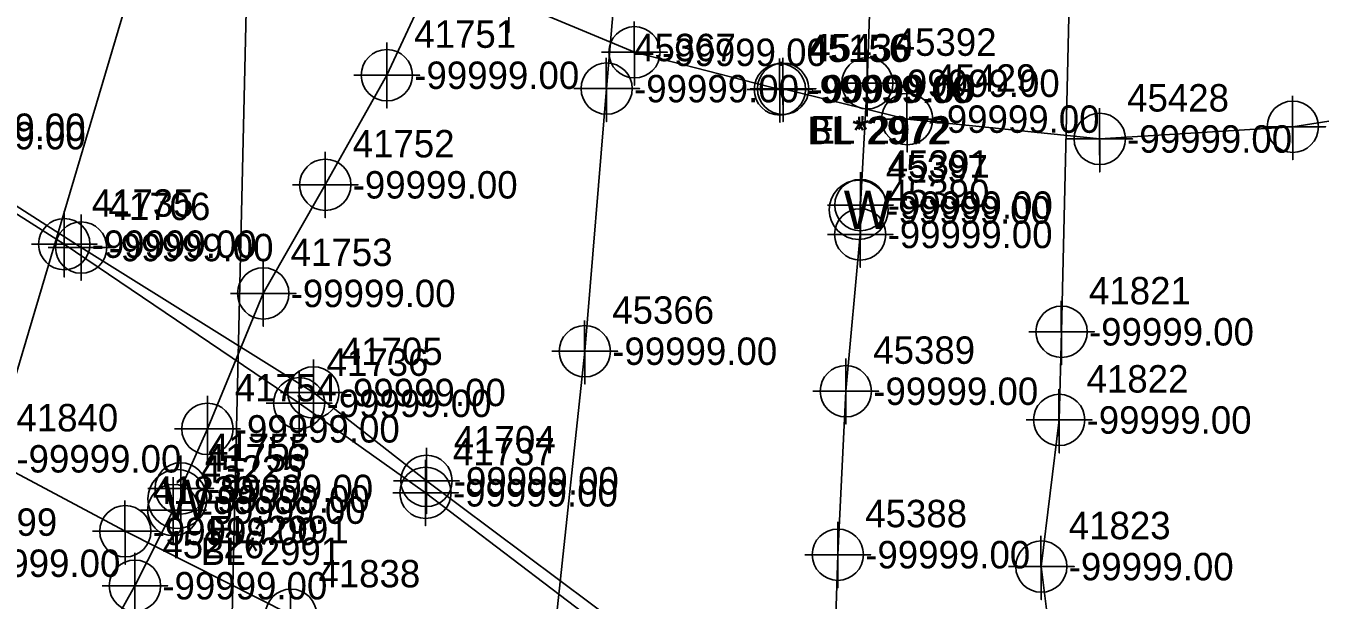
# Model space of a CAD drawing. Extents: x 2083698 to 2094313, y 743246 to 752873.
# Drawn here: x 2093554.6 to 2093672.8, y 743931 to 743983.3 of the extents above; entities that cross this region are included whole.
import ezdxf

# ---------------------------------------------------------------- set-up
doc = ezdxf.new("R2010")
doc.units = 0
for name, color, linetype in [('COGO Default Point Number', 7, 'Continuous'), ('Default Symbol CELL', 7, 'Continuous'), ('Default Symbol Cogo Number', 7, 'Continuous'), ('Exist Property Line', 7, 'Continuous'), ('Exist Property Line Leader', 7, 'Continuous'), ('Exist Right of Way Line', 7, 'Continuous'), ('Exist Right of Way Line Leader', 7, 'Continuous'), ('Exist Right of Way Line Text', 7, 'Continuous'), ('Exist Right of Way Width CELL', 7, 'Continuous'), ('Exist Utilities Power Pole Cogo Comment', 7, 'Continuous'), ('Exist Utilities Power Pole Cogo Elevation', 7, 'Continuous'), ('Exist Utilities Power Pole Cogo Number', 7, 'Continuous'), ('Exist Utilities Power UG Cable SUE LOS C', 7, 'Continuous'), ('Exist Utilities Telephone UG Conduit SUE LOS B', 7, 'Continuous'), ('Exist Utilities Telephone UG Conduit SUE LOS D', 7, 'Continuous'), ('Exist Utilities TV UG Cable SUE LOS B', 7, 'Continuous'), ('Exist Utilities Water UG Line SUE LOS B', 7, 'Continuous'), ('Scratch_Level_2', 7, 'Continuous'), ('Scratch_Level_3', 7, 'Continuous')]:
    doc.layers.add(name, color=color, linetype=linetype)

msp = doc.modelspace()

# ---------------------------------------------------------------- linework, layer by layer
at = {"layer": 'COGO Default Point Number'}
for points in [[(2093587.59, 743981.82), (2093587.59, 743975.82), (2093587.59, 743978.82), (2093590.59, 743978.82), (2093584.59, 743978.82)], [(2093631.44, 743981.09), (2093631.44, 743975.09), (2093631.44, 743978.09), (2093634.44, 743978.09), (2093628.44, 743978.09)], [(2093581.97, 743971.83), (2093581.97, 743965.83), (2093581.97, 743968.83), (2093584.97, 743968.83), (2093578.97, 743968.83)], [(2093630.81, 743969.98), (2093630.81, 743963.98), (2093630.81, 743966.98), (2093633.81, 743966.98), (2093627.81, 743966.98)], [(2093630.79, 743967.31), (2093630.79, 743961.31), (2093630.79, 743964.31), (2093633.79, 743964.31), (2093627.79, 743964.31)], [(2093576.31, 743961.93), (2093576.31, 743955.93), (2093576.31, 743958.93), (2093579.31, 743958.93), (2093573.31, 743958.93)], [(2093629.48, 743953.01), (2093629.48, 743947.01), (2093629.48, 743950.01), (2093632.48, 743950.01), (2093626.48, 743950.01)], [(2093571.21, 743949.58), (2093571.21, 743943.58), (2093571.21, 743946.58), (2093574.21, 743946.58), (2093568.21, 743946.58)], [(2093568.78, 743944.15), (2093568.78, 743938.15), (2093568.78, 743941.15), (2093571.78, 743941.15), (2093565.78, 743941.15)], [(2093568.1, 743942.17), (2093568.1, 743936.17), (2093568.1, 743939.17), (2093571.1, 743939.17), (2093565.1, 743939.17)], [(2093628.75, 743938.11), (2093628.75, 743932.11), (2093628.75, 743935.11), (2093631.75, 743935.11), (2093625.75, 743935.11)], [(2093564.6, 743935.28), (2093564.6, 743929.28), (2093564.6, 743932.28), (2093567.6, 743932.28), (2093561.6, 743932.28)]]:
    msp.add_lwpolyline(points, dxfattribs=at)
for centre in [(2093587.59, 743978.82), (2093631.44, 743978.09), (2093581.97, 743968.83), (2093630.81, 743966.98), (2093630.79, 743964.31), (2093576.31, 743958.93), (2093629.48, 743950.01), (2093571.21, 743946.58), (2093568.78, 743941.15), (2093568.1, 743939.17), (2093628.75, 743935.11), (2093564.6, 743932.28)]:
    msp.add_circle(centre, 2.34, dxfattribs=at)
at = {"layer": 'Exist Property Line Leader'}
for points in [[(2093558.15, 743966.42), (2093558.15, 743960.42), (2093558.15, 743963.42), (2093561.15, 743963.42), (2093555.15, 743963.42)], [(2093559.69, 743966.11), (2093559.69, 743960.11), (2093559.69, 743963.11), (2093562.69, 743963.11), (2093556.69, 743963.11)], [(2093580.89, 743952.9), (2093580.89, 743946.9), (2093580.89, 743949.9), (2093583.89, 743949.9), (2093577.89, 743949.9)], [(2093579.59, 743951.91), (2093579.59, 743945.91), (2093579.59, 743948.91), (2093582.59, 743948.91), (2093576.59, 743948.91)], [(2093591.2, 743944.84), (2093591.2, 743938.84), (2093591.2, 743941.84), (2093594.2, 743941.84), (2093588.2, 743941.84)], [(2093591.12, 743943.75), (2093591.12, 743937.75), (2093591.12, 743940.75), (2093594.12, 743940.75), (2093588.12, 743940.75)]]:
    msp.add_lwpolyline(points, dxfattribs=at)
for centre in [(2093558.15, 743963.42), (2093559.69, 743963.11), (2093579.59, 743948.91), (2093580.89, 743949.9), (2093591.2, 743941.84), (2093591.12, 743940.75)]:
    msp.add_circle(centre, 2.34, dxfattribs=at)
at = {"layer": 'Exist Right of Way Line Text'}
for points in [[(2093598.69, 743988.55), (2093598.72, 743982.74), (2093598.7, 743985.74), (2093601.72, 743985.74), (2093595.72, 743985.74)], [(2093610.16, 743983.73), (2093610.19, 743977.91), (2093610.18, 743980.91), (2093613.19, 743980.91), (2093607.19, 743980.91)], [(2093607.62, 743980.42), (2093607.65, 743974.6), (2093607.64, 743977.6), (2093610.65, 743977.6), (2093604.65, 743977.6)], [(2093623.43, 743980.34), (2093623.46, 743974.53), (2093623.44, 743977.53), (2093626.46, 743977.53), (2093620.46, 743977.53)], [(2093623.72, 743980.4), (2093623.75, 743974.59), (2093623.73, 743977.59), (2093626.75, 743977.59), (2093620.75, 743977.59)], [(2093635.05, 743977.64), (2093635.08, 743971.82), (2093635.06, 743974.82), (2093638.08, 743974.82), (2093632.08, 743974.82)], [(2093670.24, 743976.94), (2093670.27, 743971.12), (2093670.25, 743974.12), (2093673.27, 743974.12), (2093667.27, 743974.12)], [(2093652.62, 743975.83), (2093652.65, 743970.01), (2093652.64, 743973.01), (2093655.65, 743973.01), (2093649.65, 743973.01)], [(2093649.14, 743958.24), (2093649.17, 743952.43), (2093649.15, 743955.43), (2093652.17, 743955.43), (2093646.17, 743955.43)], [(2093605.63, 743956.47), (2093605.66, 743950.66), (2093605.65, 743953.66), (2093608.66, 743953.66), (2093602.66, 743953.66)], [(2093648.91, 743950.2), (2093648.95, 743944.39), (2093648.93, 743947.39), (2093651.95, 743947.39), (2093645.95, 743947.39)], [(2093563.69, 743940.05), (2093563.72, 743934.24), (2093563.7, 743937.24), (2093566.72, 743937.24), (2093560.72, 743937.24)], [(2093647.29, 743936.83), (2093647.32, 743931.02), (2093647.31, 743934.02), (2093650.32, 743934.02), (2093644.32, 743934.02)], [(2093578.8, 743932.45), (2093578.84, 743926.63), (2093578.82, 743929.63), (2093581.84, 743929.63), (2093575.84, 743929.63)]]:
    msp.add_lwpolyline(points, dxfattribs=at)
for centre in [(2093610.19, 743980.91), (2093607.65, 743977.6), (2093623.46, 743977.53), (2093623.75, 743977.59), (2093635.08, 743974.82), (2093670.27, 743974.12), (2093652.65, 743973.01), (2093649.17, 743955.43), (2093605.66, 743953.66), (2093648.95, 743947.39), (2093563.72, 743937.24), (2093647.32, 743934.02), (2093578.84, 743929.63)]:
    msp.add_circle(centre, 2.34, dxfattribs=at)
at = {"layer": 'Exist Utilities Power Pole Cogo Number'}
for p, q in [((2093630.64, 743966.54), (2093630.64, 743966.54)), ((2093568.47, 743940.19), (2093568.47, 743940.19))]:
    msp.add_line(p, q, dxfattribs=at)
for centre in [(2093630.64, 743966.55), (2093568.46, 743940.19)]:
    msp.add_circle(centre, 2.69, dxfattribs=at)
at = {"layer": 'Exist Utilities Power UG Cable SUE LOS C'}
msp.add_line((2093454.44, 743617.61), (2093577.14, 744030.24), dxfattribs=at)
at = {"layer": 'Exist Utilities Telephone UG Conduit SUE LOS B'}
for points in [[(2093469.73, 744031.63), (2093469.78, 744031.87), (2093521.52, 744014.24), (2093530.92, 744010.38), (2093535.13, 744009.31), (2093577.89, 743996.45), (2093586.21, 743992.8), (2093598.72, 743985.74), (2093610.19, 743980.91), (2093623.46, 743977.53)], [(2093650.51, 744031.9), (2093649.34, 744008.67), (2093649.89, 743986.79), (2093649.17, 743955.43), (2093648.95, 743947.39), (2093647.32, 743934.02), (2093648.38, 743925.52), (2093648.75, 743917.89), (2093648.25, 743913.04), (2093648.16, 743908.51)], [(2093580.1, 743909.04), (2093582.03, 743906.7), (2093586.73, 743900.67), (2093595.74, 743887.01), (2093599.05, 743897.45), (2093601, 743910.18), (2093605.66, 743953.66), (2093607.65, 743977.6), (2093609.08, 743994.27), (2093610.19, 744020.59)], [(2093431.96, 743997.98), (2093437.69, 743992.95), (2093453.45, 743985.76), (2093468.05, 743979.71), (2093480.68, 743974.35), (2093489.23, 743970.88), (2093489.03, 743970.7), (2093507.4, 743962.68), (2093516.24, 743958.73), (2093516.33, 743958.67), (2093535.61, 743951.44), (2093551.28, 743943.85), (2093563.72, 743937.24), (2093578.84, 743929.63), (2093591.46, 743925.91), (2093602.51, 743918.93), (2093614.21, 743910.78), (2093620.35, 743907.59), (2093636.17, 743901.89), (2093642.65, 743900.2), (2093645.84, 743899.58), (2093648.65, 743902.06), (2093648.92, 743905.27)], [(2093623.75, 743977.59), (2093635.08, 743974.82), (2093652.65, 743973.01), (2093670.27, 743974.12), (2093691.89, 743977.53), (2093711.44, 743980.25)]]:
    msp.add_lwpolyline(points, dxfattribs=at)
at = {"layer": 'Exist Utilities Telephone UG Conduit SUE LOS D'}
msp.add_lwpolyline([(2093729.86, 746559.98), (2093729.86, 746485.51), (2093728.61, 746416.16), (2093711.62, 746127.01), (2093702.37, 745955.82), (2093693.11, 745784.64), (2093668.68, 745395.41), (2093654.74, 745161.51), (2093649.12, 745054.6), (2093640.35, 744903.62), (2093631.77, 744751.08), (2093623.85, 744627.43), (2093615.93, 744503.79), (2093603.66, 744373.9), (2093590.72, 744165.44), (2093582.98, 744085.27), (2093575.24, 744005.11), (2093571.65, 743852.76), (2093573.5, 743810.29), (2093555.01, 743734.28)], dxfattribs=at)
at = {"layer": 'Exist Utilities TV UG Cable SUE LOS B'}
for points in [[(2093322.23, 744016.47), (2093331.29, 744014.12), (2093348.72, 744011.44), (2093372.64, 744006.81), (2093386.05, 744003.83), (2093398.83, 744000.56), (2093416.4, 743997.85), (2093426.12, 743996.92), (2093436.74, 743994.55), (2093460.81, 743990.43), (2093489.28, 743984.11), (2093510.62, 743979.17), (2093535.59, 743977.61), (2093542.54, 743974.08), (2093559.69, 743963.11), (2093580.89, 743949.9), (2093591.2, 743941.84), (2093615.29, 743923.85)], [(2093321.96, 744015.64), (2093330.55, 744013.59), (2093348.11, 744010.53), (2093372.2, 744005.43), (2093386.66, 744001.95), (2093398.6, 743999.59), (2093416.57, 743997.2), (2093427.18, 743995.96), (2093437.83, 743993.58), (2093460.74, 743989.8), (2093489.4, 743982.77), (2093510.1, 743978.63), (2093531.97, 743976.43), (2093542.55, 743973.31), (2093558.15, 743963.42), (2093579.59, 743948.91), (2093591.12, 743940.75), (2093614.89, 743922.71)]]:
    msp.add_lwpolyline(points, dxfattribs=at)
at = {"layer": 'Exist Utilities Water UG Line SUE LOS B'}
for points in [[(2093633.42, 744029.55), (2093632.33, 744015.99), (2093632.54, 744003.89), (2093631.93, 743993.39), (2093631.44, 743978.09), (2093630.81, 743966.98), (2093630.79, 743964.31), (2093629.48, 743950.01), (2093628.75, 743935.11), (2093628.39, 743923.88), (2093628.12, 743906.78), (2093628.31, 743895.1), (2093627.55, 743880.61), (2093625.92, 743867.19), (2093624.59, 743863.24), (2093623.47, 743860.99), (2093621.33, 743855.23)], [(2093598.52, 744012.09), (2093596.82, 744002.27), (2093592.31, 743988.96), (2093587.59, 743978.82), (2093581.97, 743968.83), (2093576.31, 743958.93), (2093571.21, 743946.58), (2093568.78, 743941.15)], [(2093568.1, 743939.17), (2093564.6, 743932.28), (2093560.29, 743924.58), (2093552.73, 743909.06), (2093545.46, 743895.78), (2093541.22, 743879.44)]]:
    msp.add_lwpolyline(points, dxfattribs=at)

# ---------------------------------------------------------------- texts
at = {"layer": 'Default Symbol CELL'}
for s, p in [('41735', (2093560.65, 743965.92)), ('41706', (2093562.19, 743965.61)), ('41705', (2093583.39, 743952.4)), ('41736', (2093582.09, 743951.41)), ('41704', (2093593.7, 743944.34)), ('41737', (2093593.62, 743943.25))]:
    msp.add_text(s, height=2.5, dxfattribs=at).set_placement(p)
at = {"layer": 'Default Symbol Cogo Number'}
for p in [(2093545.04, 743972.83), (2093545.05, 743972.06), (2093560.65, 743962.17), (2093562.19, 743961.86), (2093583.39, 743948.65), (2093582.09, 743947.66), (2093593.7, 743940.59), (2093593.62, 743939.5)]:
    msp.add_text('-99999.00', height=2.5, dxfattribs=at).set_placement(p)
at = {"layer": 'Exist Property Line'}
for p in [(2093590.09, 743977.57), (2093633.94, 743976.84), (2093584.47, 743967.58), (2093633.31, 743965.73), (2093633.29, 743963.06), (2093578.81, 743957.68), (2093631.98, 743948.76), (2093573.71, 743945.33), (2093571.28, 743939.9), (2093570.6, 743937.92), (2093631.25, 743933.86), (2093567.1, 743931.03)]:
    msp.add_text('-99999.00', height=2.5, dxfattribs=at).set_placement(p)
at = {"layer": 'Exist Right of Way Line'}
for s, p in [('41751', (2093590.09, 743981.32)), ('45392', (2093633.94, 743980.59)), ('41752', (2093584.47, 743971.33)), ('45391', (2093633.31, 743969.48)), ('45390', (2093633.29, 743966.81)), ('41753', (2093578.81, 743961.43)), ('45389', (2093631.98, 743952.51)), ('41754', (2093573.71, 743949.08)), ('41755', (2093571.28, 743943.65)), ('45225', (2093570.6, 743941.67)), ('45388', (2093631.25, 743937.61)), ('45226', (2093567.1, 743934.78))]:
    msp.add_text(s, height=2.5, dxfattribs=at).set_placement(p)
at = {"layer": 'Exist Right of Way Line Leader'}
for s, p in [('45367', (2093610.15, 743980.1)), ('45156', (2093625.96, 743980.03)), ('45430', (2093626.25, 743980.09)), ('45429', (2093637.58, 743977.32)), ('45428', (2093655.15, 743975.51)), ('41821', (2093651.67, 743957.93)), ('45366', (2093608.16, 743956.16)), ('41822', (2093651.45, 743949.89)), ('41840', (2093553.78, 743946.35)), ('41839', (2093566.22, 743939.74)), ('45199', (2093548.21, 743936.83)), ('41823', (2093649.82, 743936.52)), ('41838', (2093581.34, 743932.13))]:
    msp.add_text(s, height=2.5, dxfattribs=at).set_placement(p)
at = {"layer": 'Exist Right of Way Width CELL'}
for s, p in [('EL*2991', (2093571.28, 743936.15)), ('BL*2991', (2093570.6, 743934.17))]:
    msp.add_text(s, height=2.5, dxfattribs=at).set_placement(p)
at = {"layer": 'Exist Utilities Power Pole Cogo Comment'}
for p in [(2093633.14, 743965.29), (2093570.97, 743938.94)]:
    msp.add_text('-99999.00', height=2.5, dxfattribs=at).set_placement(p)
at = {"layer": 'Exist Utilities Power Pole Cogo Elevation'}
for s, p in [('45397', (2093633.14, 743969.04)), ('41756', (2093570.97, 743942.69))]:
    msp.add_text(s, height=2.5, dxfattribs=at).set_placement(p)
at = {"layer": 'Exist Utilities Power Pole Cogo Number'}
for p in [(2093629.29, 743964.79), (2093567.11, 743938.44)]:
    msp.add_text('W', height=3.5, dxfattribs=at).set_placement(p)
at = {"layer": 'Scratch_Level_2'}
for p in [(2093612.69, 743979.66), (2093610.15, 743976.35), (2093625.96, 743976.28), (2093626.25, 743976.34), (2093637.58, 743973.57), (2093655.15, 743971.76), (2093651.67, 743954.18), (2093608.16, 743952.41), (2093651.45, 743946.14), (2093553.78, 743942.6), (2093566.22, 743935.99), (2093548.21, 743933.08), (2093649.82, 743932.77)]:
    msp.add_text('-99999.00', height=2.5, dxfattribs=at).set_placement(p)
at = {"layer": 'Scratch_Level_3'}
for s, p in [('BL*2972', (2093625.96, 743972.53)), ('EL*2972', (2093626.25, 743972.59))]:
    msp.add_text(s, height=2.5, dxfattribs=at).set_placement(p)

doc.saveas('drawing.dxf')
